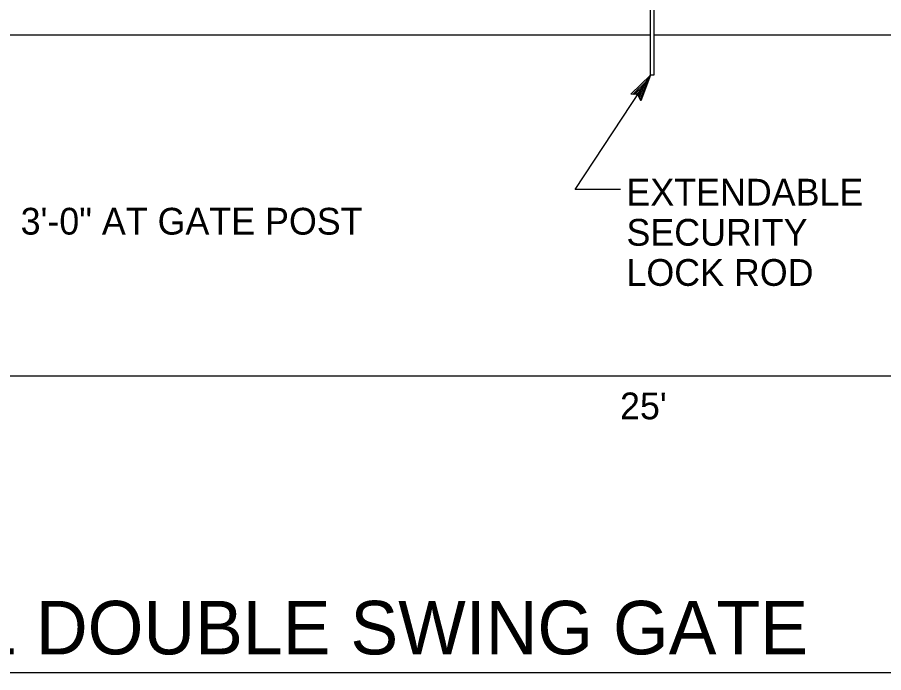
# Model space of a CAD drawing. Extents: x -121933 to -117742, y -103160 to -100084.
# Drawn here: x -121160 to -120965.9, y -102524.1 to -102377.2 of the extents above; entities that cross this region are included whole.
import ezdxf

# ---------------------------------------------------------------- set-up
doc = ezdxf.new("R2010")
doc.units = 0
for name, color, linetype in [('G-MARK', 7, 'Continuous'), ('Misc CnstDet(22)', 7, 'Continuous'), ('Nongeo Data(60)', 7, 'Continuous')]:
    doc.layers.add(name, color=color, linetype=linetype)

msp = doc.modelspace()

# ---------------------------------------------------------------- linework, layer by layer
at = {"layer": 'G-MARK'}
for p, q in [((-121034.97, -102415.84), (-121018.08, -102390.2)), ((-121022.5, -102394.47), (-121018.08, -102390.2)), ((-121022.09, -102394.49), (-121018.84, -102391.35)), ((-121018.85, -102391.36), (-121020.44, -102395.55)), ((-121018.08, -102390.2), (-121020.27, -102395.94)), ((-121018.08, -102390.2), (-121018.08, -102390.2)), ((-121021.66, -102394.49), (-121019.6, -102392.51)), ((-121019.6, -102392.51), (-121020.64, -102395.21)), ((-121020.94, -102394.54), (-121022.5, -102394.47)), ((-121022.5, -102394.47), (-121022.5, -102394.47)), ((-121021.27, -102394.54), (-121020.37, -102393.66)), ((-121020.27, -102395.94), (-121020.94, -102394.54)), ((-121020.37, -102393.66), (-121020.81, -102394.82)), ((-121020.27, -102395.94), (-121020.27, -102395.94)), ((-121024.83, -102415.84), (-121034.97, -102415.84)), ((-121220.62, -102457.55), (-120808.19, -102457.55))]:
    msp.add_line(p, q, dxfattribs=at)
at = {"layer": 'Misc CnstDet(22)'}
msp.add_line((-120905.86, -102524.14), (-121238.29, -102524.14), dxfattribs=at)
msp.add_lwpolyline([(-121017.32, -102375.24), (-121017.32, -102390.2), (-121018.08, -102390.2), (-121018.08, -102375.24)], dxfattribs=at)
at = {"layer": 'Nongeo Data(60)'}
for p, q in [((-121018.08, -102381.24), (-121220.7, -102381.24)), ((-121014.39, -102381.24), (-121017.32, -102381.24)), ((-120810.39, -102381.24), (-121014.39, -102381.24))]:
    msp.add_line(p, q, dxfattribs=at)

# ---------------------------------------------------------------- texts
at = {"layer": 'Misc CnstDet(22)'}
for s, height, p in [('EXTENDABLE', 6, (-121023.48, -102419.41)), ('3\'-0" AT GATE POST', 6, (-121159.21, -102425.92)), ('SECURITY', 6, (-121023.48, -102428.41)), ('LOCK ROD', 6, (-121023.48, -102437.41)), ('MANUAL DOUBLE SWING GATE', 12, (-121227.11, -102520.04))]:
    msp.add_text(s, height=height, dxfattribs=at).set_placement(p)
at = {"layer": 'Nongeo Data(60)'}
msp.add_text("25'", height=6, dxfattribs=at).set_placement((-121024.92, -102467.33))

doc.saveas('drawing.dxf')
